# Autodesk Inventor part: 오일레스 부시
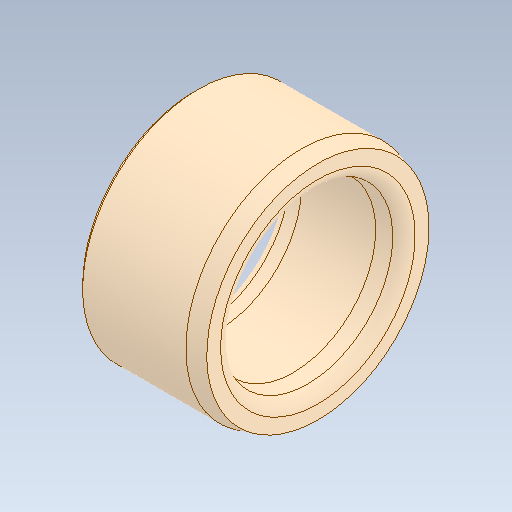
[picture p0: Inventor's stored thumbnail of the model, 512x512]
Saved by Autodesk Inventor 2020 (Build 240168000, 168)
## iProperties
Created: 2024-05
Part Number: 오일레스 부시
Material: 구리, 합금
Document SubType Name: Modeling
Designer: oem
Density: 8.92 g/cm^3
Appearance: 기본값
Author: jhkim
Sending System: Autodesk Inventor 2025
Preprocessor: ST-DEVELOPER v20
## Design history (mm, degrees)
feature "솔리드1"
node "솔리드2"
